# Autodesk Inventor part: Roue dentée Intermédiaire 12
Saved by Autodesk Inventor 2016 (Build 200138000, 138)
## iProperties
Created: 2013-08
Part Number: Roue dentée Intermédiaire 12
Material: Générique
Document SubType Name: Modeling
Designer: hilarion
Density: 1 g/cm^3
Appearance: Par défaut
Author: Balduini Gael & Faure Olivier
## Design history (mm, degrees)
node "Roue dentée Intermédiaire 121"
node "Roue dentée Intermédiaire 12"
node "Roue dentée Intermédiaire 12_1"
node "Base1"
node "Base2"
